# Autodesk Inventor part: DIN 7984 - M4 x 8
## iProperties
IsCustomPart: 0
Created: 2009-02
Part Number: DIN 7984 - M4 x 8
Material: Stahl, weich, unlegiert
Description: Zylinderkopfschraube
Document SubType Name: Modeling
Standard: DIN 7984
Designer: UR
Standard Revision: 1985
Standards Organization: DIN
Language: de-DE
Size Designation: M4 x 8
Categories: <MemberInstance><Categories><Category DisplayName="Verbindungselemente" InternalName="e4da775c-781d-43d5-af7c-5136215cf5a6" Mnemonic="FSTN"><Category DisplayNam
Density: 1 g/cm^3
Author: UR
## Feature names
1. Körper [Revolution]
2. Loch [Extrusion]
3. Rundung1 [Fillet]
4. Fase1 [Chamfer]
5. Fillet2
